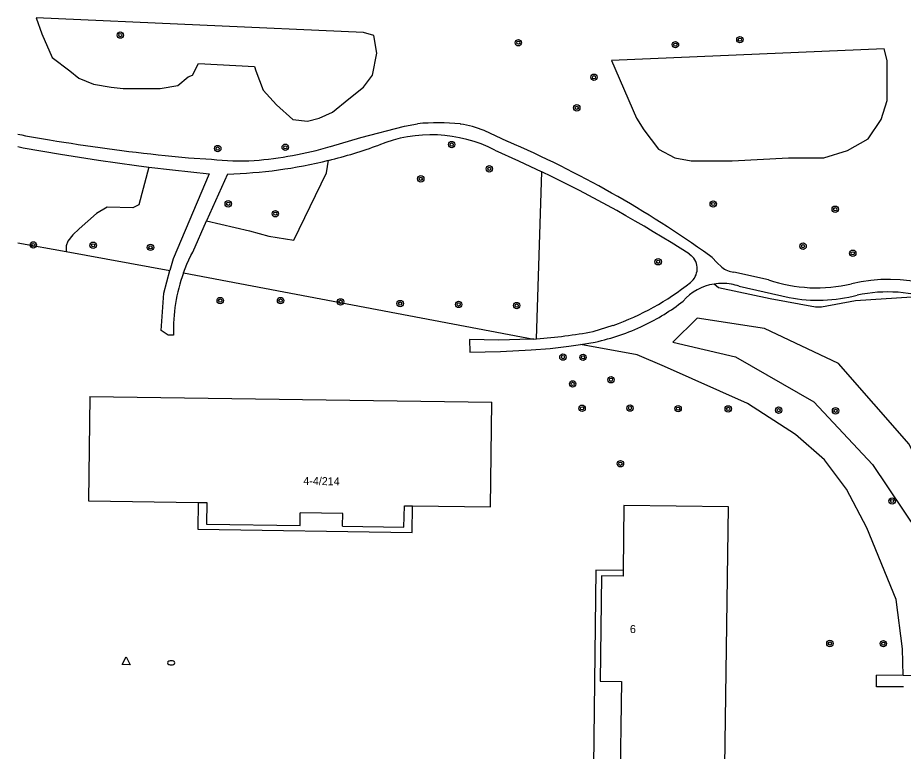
# Model space of a CAD drawing. Extents: x 132573 to 132944, y 398226 to 398676.
# Drawn here: x 132573 to 132683.7, y 398438.1 to 398529.7 of the extents above; entities that cross this region are included whole.
import ezdxf

# ---------------------------------------------------------------- set-up
doc = ezdxf.new("R2010")
doc.units = 0
for name, color, linetype in [('gg-anno-huisnummerreeks BGT', 7, 'Continuous'), ('gg-bbg-hoofdgebouw', 7, 'Continuous'), ('gg-bbg-luifel en loopbrug', 7, 'Continuous'), ('gg-knt-verharding', 7, 'Continuous'), ('gt-grn-groengrens', 7, 'Continuous'), ('gt-symb-boom', 7, 'Continuous'), ('gt-symb-brandkraan', 7, 'Continuous'), ('gt-symb-waterafsluiter', 7, 'Continuous')]:
    doc.layers.add(name, color=color, linetype=linetype)

msp = doc.modelspace()

# ---------------------------------------------------------------- linework, layer by layer
at = {"layer": 'gg-bbg-hoofdgebouw'}
msp.add_line((132582.04, 398482.36), (132632.27, 398481.66), dxfattribs=at)
for points in [[(132582.04, 398482.36), (132581.87, 398469.33), (132595.58, 398469.14)], [(132622.36, 398468.73), (132632.09, 398468.61), (132632.27, 398481.66)], [(132595.58, 398469.14), (132596.63, 398469.12), (132596.62, 398466.45), (132608.3, 398466.25), (132608.33, 398467.85)], [(132613.6, 398466.19), (132621.27, 398466.07), (132621.33, 398468.74), (132622.36, 398468.73)], [(132648.26, 398432.7), (132648.15, 398424.66), (132661.2, 398424.41), (132661.81, 398468.58), (132648.76, 398468.75), (132648.66, 398460.63)], [(132613.6, 398466.19), (132613.63, 398467.77), (132608.33, 398467.85)], [(132648.66, 398460.63), (132648.65, 398459.94), (132645.95, 398459.98), (132645.78, 398446.81)], [(132645.78, 398446.81), (132648.46, 398446.77), (132648.26, 398432.7)]]:
    msp.add_lwpolyline(points, dxfattribs=at)
at = {"layer": 'gg-bbg-luifel en loopbrug'}
for points in [[(132595.58, 398469.14), (132595.54, 398465.81), (132622.32, 398465.4), (132622.36, 398468.73)], [(132648.66, 398460.63), (132645.27, 398460.67), (132644.9, 398432.74), (132648.26, 398432.7)]]:
    msp.add_lwpolyline(points, dxfattribs=at)
at = {"layer": 'gg-knt-verharding'}
for p, q in [((132634.23, 398514.23), (132631.31, 398515.6)), ((132599.22, 398510.16), (132596.62, 398504.33)), ((132656.9, 398500.19), (132657.16, 398500)), ((132666.81, 398496.96), (132662.5, 398497.89)), ((132663.15, 398496.15), (132669.4, 398494.76)), ((132644.92, 398490.5), (132647.42, 398491.27)), ((132637.51, 398489.56), (132637.85, 398489.59)), ((132641.88, 398488.65), (132643.33, 398488.89)), ((132643.33, 398488.89), (132645.17, 398489.18)), ((132683.65, 398447.54), (132680.31, 398447.58)), ((132688.61, 398447.48), (132683.65, 398447.54))]:
    msp.add_line(p, q, dxfattribs=at)
for points in [[(132612.08, 398513.6), (132615.88, 398514.72), (132621.33, 398516.16), (132622.96, 398516.45)], [(132573.02, 398513.61), (132573.72, 398513.46), (132578.36, 398512.65), (132583.1, 398511.9), (132587.85, 398511.23), (132589.42, 398511.04)], [(132632.65, 398513.15), (132635.6, 398511.83), (132638.52, 398510.45)], [(132591.46, 398512.49), (132594.34, 398512.2), (132597.23, 398512.01)], [(132589.42, 398511.04), (132592.38, 398510.68), (132596.92, 398510.2), (132592.44, 398499.59), (132592.04, 398498.12)], [(132593.73, 398497.82), (132594.17, 398498.92), (132594.67, 398500), (132594.88, 398500.41), (132596.62, 398504.33)], [(132660.99, 398498.53), (132660.35, 398499.11), (132659.77, 398499.76), (132659.43, 398500)], [(132592.48, 398490.05), (132591.81, 398490.05), (132590.94, 398490.63), (132591.26, 398495.29), (132592.04, 398498.12)], [(132637.51, 398489.56), (132637.1, 398489.54), (132633.13, 398489.43), (132629.46, 398489.48), (132629.49, 398487.93), (132633.34, 398488), (132637.18, 398488.2), (132639.53, 398488.38), (132641.88, 398488.65)], [(132683.68, 398446.1), (132680.32, 398446.11), (132680.31, 398447.58)]]:
    msp.add_lwpolyline(points, dxfattribs=at)
for centre, radius, start, end in [((132625.47, 398486.93), 29.63, 84.4782, 94.8592), ((132626.72, 398504.69), 11.83, 67.2004, 82.2309), ((132595.3, 398630.1), 117.1, 259.0329, 261.0059), ((132615.05, 398742.1), 230.82, 260.5086, 264.1335), ((132624.69, 398497.6), 17.47, 62.9098, 112.0833), ((132580.63, 398389.89), 135.41, 54.409, 66.6792), ((132599.01, 398558.28), 46.55, 274.3782, 286.2983), ((132597.51, 398570.16), 60.03, 283.8236, 290.0824), ((132600.81, 398544.64), 32.83, 263.7389, 273.0603), ((132597.51, 398570.19), 60.05, 271.629, 283.8232), ((132562.18, 398352.15), 175.75, 57.3898, 64.2562), ((132655.71, 398498.34), 2.2, 308.3858, 48.9757), ((132662.87, 398500.9), 3.02, 231.4159, 262.8931), ((132613.17, 398490.72), 20.69, 159.9435, 181.8645), ((132636.05, 398523.21), 33.91, 289.5847, 308.3269), ((132661.02, 398490.05), 6.46, 98.9358, 138.9367), ((132661.02, 398490.04), 6.47, 79.7458, 98.9261), ((132661.02, 398490.02), 6.49, 70.7622, 79.7103), ((132672.88, 398514.53), 18.58, 250.9529, 283.4324), ((132681.87, 398476.66), 20.34, 48.3341, 103.2958), ((132681.7, 398477.09), 18.35, 69.8509, 101.9393), ((132640.24, 398514.5), 25.72, 295.2807, 308.2231), ((132673.02, 398513.75), 19.34, 259.2259, 284.6283), ((132638.97, 398517.28), 28.78, 282.4325, 295.1857), ((132633.55, 398550.91), 61.47, 274.0061, 280.6565)]:
    msp.add_arc(centre, radius, start, end, dxfattribs=at)
at = {"layer": 'gt-grn-groengrens'}
for p, q in [((132637.85, 398489.59), (132638.52, 398510.45)), ((132573.02, 398501.59), (132579.08, 398500.5)), ((132579.08, 398500.5), (132592.04, 398498.12)), ((132593.73, 398497.82), (132637.51, 398489.56))]:
    msp.add_line(p, q, dxfattribs=at)
for points in [[(132575.32, 398529.69), (132576.05, 398527.67), (132577.34, 398524.72), (132579.55, 398523.06), (132580.66, 398522.14), (132582.5, 398521.4), (132584.71, 398521.03), (132586.19, 398520.85), (132590.8, 398520.85), (132593.01, 398521.22), (132594.3, 398522.32), (132594.85, 398522.51), (132595.59, 398523.98), (132602.59, 398523.61), (132602.77, 398523.06), (132603.7, 398520.66), (132605.36, 398518.82), (132607.38, 398516.98), (132609.23, 398516.79), (132610.7, 398517.16), (132612.36, 398517.9), (132614.39, 398519.56), (132616.23, 398521.03), (132617.33, 398522.51), (132617.89, 398525.27), (132617.52, 398527.48), (132616.23, 398527.85), (132575.32, 398529.69)], [(132647.19, 398524.35), (132650.32, 398517.16), (132651.24, 398515.69), (132653.09, 398513.29), (132655.11, 398512.18), (132657.14, 398511.82), (132662.3, 398511.82), (132669.3, 398512.18), (132673.73, 398512.18), (132676.68, 398513.11), (132679.26, 398514.58), (132680.91, 398516.98), (132681.65, 398519.37), (132681.65, 398524.35), (132681.28, 398525.82), (132647.19, 398524.35)], [(132596.62, 398504.33), (132601.99, 398503.06), (132604.38, 398502.39), (132607.5, 398501.91), (132611.59, 398510.3), (132611.86, 398511.88)], [(132589.42, 398511.04), (132588.14, 398506.33), (132587.41, 398505.96), (132584.19, 398506.04), (132582.86, 398505.24), (132580.68, 398503.31), (132579.89, 398502.57), (132579.29, 398501.77), (132579.07, 398501.18), (132579.08, 398500.5)], [(132687.59, 398493.54), (132684.73, 398494.77), (132677.7, 398494.35), (132673.45, 398493.53), (132672.69, 398493.52), (132667.02, 398494.58), (132660.59, 398495.97), (132660.02, 398496.43)], [(132688.08, 398455.37), (132690.94, 398456.38), (132690.03, 398465.16), (132684.38, 398476.41), (132675.57, 398486.51), (132666.33, 398490.87), (132657.92, 398492.15), (132654.85, 398489.18), (132662.7, 398487.34), (132672.48, 398481.71), (132679.83, 398473.9), (132685.51, 398465.41), (132688.08, 398455.37)], [(132683.65, 398447.54), (132683.58, 398450.86), (132682.79, 398457.01), (132679.11, 398465.96), (132676.56, 398470.81), (132673.8, 398474.49), (132670.2, 398477.63), (132664.21, 398481.5), (132653.83, 398486.12), (132650.42, 398487.59), (132643.33, 398488.89)]]:
    msp.add_lwpolyline(points, dxfattribs=at)
at = {"layer": 'gt-symb-boom'}
for centre, radius in [((132585.84, 398527.52), 0.4), ((132585.84, 398527.52), 0.2), ((132663.25, 398526.95), 0.4), ((132635.57, 398526.57), 0.4), ((132635.57, 398526.57), 0.2), ((132655.19, 398526.33), 0.4), ((132655.19, 398526.33), 0.2), ((132663.25, 398526.95), 0.2), ((132645.02, 398522.26), 0.4), ((132645.02, 398522.26), 0.2), ((132642.87, 398518.44), 0.4), ((132642.87, 398518.44), 0.2), ((132627.24, 398513.85), 0.4), ((132627.24, 398513.85), 0.2), ((132598.01, 398513.35), 0.4), ((132598.01, 398513.35), 0.2), ((132606.45, 398513.51), 0.4), ((132606.45, 398513.51), 0.2), ((132631.94, 398510.82), 0.4), ((132631.94, 398510.82), 0.2), ((132623.38, 398509.57), 0.4), ((132623.38, 398509.57), 0.2), ((132599.32, 398506.45), 0.4), ((132599.32, 398506.45), 0.2), ((132659.92, 398506.43), 0.4), ((132659.92, 398506.43), 0.2), ((132605.21, 398505.21), 0.4), ((132605.21, 398505.21), 0.2), ((132675.16, 398505.77), 0.4), ((132675.16, 398505.77), 0.2), ((132574.97, 398501.31), 0.4), ((132574.97, 398501.31), 0.2), ((132582.45, 398501.27), 0.4), ((132582.45, 398501.27), 0.2), ((132589.61, 398501.01), 0.4), ((132589.61, 398501.01), 0.2), ((132671.14, 398501.16), 0.4), ((132671.14, 398501.16), 0.2), ((132677.35, 398500.27), 0.4), ((132677.35, 398500.27), 0.2), ((132653.04, 398499.21), 0.4), ((132653.04, 398499.21), 0.2), ((132598.32, 398494.36), 0.4), ((132598.32, 398494.36), 0.2), ((132605.86, 398494.36), 0.4), ((132605.86, 398494.36), 0.2), ((132613.36, 398494.2), 0.4), ((132613.36, 398494.2), 0.2), ((132620.8, 398493.99), 0.4), ((132620.8, 398493.99), 0.2), ((132628.11, 398493.88), 0.4), ((132635.36, 398493.74), 0.4), ((132628.11, 398493.88), 0.2), ((132635.36, 398493.74), 0.2), ((132641.14, 398487.3), 0.4), ((132641.14, 398487.3), 0.2), ((132643.65, 398487.27), 0.4), ((132643.65, 398487.27), 0.2), ((132642.35, 398483.95), 0.4), ((132642.35, 398483.95), 0.2), ((132647.15, 398484.47), 0.4), ((132647.15, 398484.47), 0.2), ((132643.53, 398480.91), 0.4), ((132643.53, 398480.91), 0.2), ((132649.52, 398480.93), 0.4), ((132649.52, 398480.93), 0.2), ((132655.53, 398480.86), 0.4), ((132655.53, 398480.86), 0.2), ((132661.79, 398480.83), 0.4), ((132661.79, 398480.83), 0.2), ((132668.09, 398480.67), 0.4), ((132668.09, 398480.67), 0.2), ((132675.2, 398480.59), 0.4), ((132675.2, 398480.59), 0.2), ((132648.32, 398473.98), 0.4), ((132648.32, 398473.98), 0.2), ((132682.27, 398469.33), 0.4), ((132682.27, 398469.33), 0.2), ((132674.49, 398451.53), 0.4), ((132674.49, 398451.53), 0.2), ((132681.17, 398451.51), 0.4), ((132681.17, 398451.51), 0.2)]:
    msp.add_circle(centre, radius, dxfattribs=at)
at = {"layer": 'gt-symb-brandkraan'}
for centre, radius, start, end in [((132591.96, 398449.12), 0.206, 106.7076, 251.5737), ((132592.85, 398451.77), 3, 251.5737, 252.2486), ((132592.77, 398446.44), 3, 106.0327, 106.7076), ((132592.22, 398449.8), 0.938, 252.2486, 286.0327), ((132592.2, 398448.42), 0.938, 72.2486, 106.0327), ((132591.57, 398446.46), 3, 71.5737, 72.2486), ((132591.65, 398451.78), 3, 286.0327, 286.7076), ((132592.45, 398449.11), 0.206, 286.7076, 71.5737)]:
    msp.add_arc(centre, radius, start, end, dxfattribs=at)
at = {"layer": 'gt-symb-waterafsluiter'}
for p, q in [((132586.08, 398448.89), (132586.59, 398449.88)), ((132586.59, 398449.88), (132587.08, 398448.88)), ((132587.08, 398448.88), (132586.08, 398448.89))]:
    msp.add_line(p, q, dxfattribs=at)

# ---------------------------------------------------------------- texts
at = {"layer": 'gg-anno-huisnummerreeks BGT'}
for s, rotation, p in [('4-4/214', 359.1, (132608.7, 398471.35)), ('6', 359.2, (132649.5, 398452.84))]:
    msp.add_text(s, height=1, rotation=rotation, dxfattribs=at).set_placement(p)

doc.saveas('drawing.dxf')
